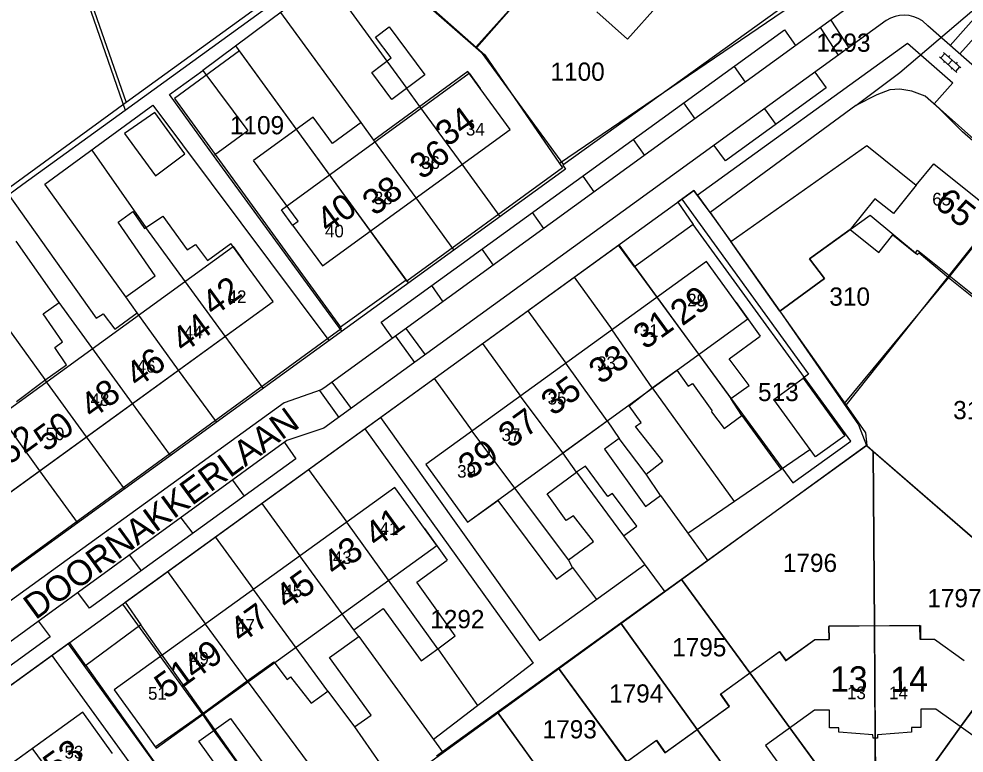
# Model space of a CAD drawing. Extents: x 148816 to 151297, y 399515 to 402500.
# Drawn here: x 149607 to 149700.3, y 400379.3 to 400451.8 of the extents above; entities that cross this region are included whole.
import ezdxf

# ---------------------------------------------------------------- set-up
doc = ezdxf.new("R2010")
doc.units = 0
for name, color, linetype in [('B01 Hoofdgebouw  [D] Norm', 7, 'Continuous'), ('B01 Hoofdgebouw  [T] Norm', 7, 'Continuous'), ('B01 hoofgebouw', 7, 'Continuous'), ('B02 Bijgebouw  [D] Norm', 7, 'Continuous'), ('B02 Bijgebouw  [T] Norm', 7, 'Continuous'), ('B07 Tussenmuur  [D] Norm', 7, 'Continuous'), ('G01 perceelsgrens', 7, 'Continuous'), ('S02 Open verharding  Norm', 7, 'Continuous'), ('T04 Haag heg  [D] Gem', 7, 'Continuous'), ('V00 Kant verharding algemeen  [T] Norm', 7, 'Continuous'), ('V00 Kant verharding algemeen secundair  [T] Gem', 7, 'Continuous'), ('Z01 perceelnummer', 7, 'Continuous'), ('Z02 huisnummer', 7, 'Continuous'), ('Z02 Huisnummer  [Tekst] Norm', 7, 'Continuous'), ('Z06 straatnaam', 7, 'Continuous')]:
    doc.layers.add(name, color=color, linetype=linetype)

msp = doc.modelspace()

# ---------------------------------------------------------------- linework, layer by layer
at = {"layer": 'B01 Hoofdgebouw  [D] Norm'}
for p, q in [((149634.541, 400431.857), (149630.161, 400437.867)), ((149634.01, 400431.47), (149634.541, 400431.857))]:
    msp.add_line(p, q, dxfattribs=at)
for points in [[(149626.206, 400438.351), (149621.85, 400444.376), (149625.142, 400446.746), (149629.575, 400440.771), (149626.282, 400438.376)], [(149652.54, 400444.97), (149651.318, 400446.638), (149642.033, 400439.87), (149640.776, 400441.593)], [(149640.776, 400441.593), (149637.939, 400439.525), (149636.029, 400442.145), (149630.161, 400437.867)], [(149605.857, 400434.609), (149614.619, 400422.278), (149615.307, 400422.706), (149616.466, 400421.2), (149618.662, 400422.788), (149617.554, 400424.396), (149620.438, 400426.463), (149616.789, 400431.773), (149618.218, 400432.806), (149619.376, 400431.147), (149621.188, 400432.356), (149623.58, 400429.012), (149624.421, 400429.54), (149625.605, 400427.957), (149627.914, 400429.66)], [(149682.127, 400422.976), (149686.543, 400426.192), (149685.056, 400428.133), (149691.029, 400432.444), (149695.729, 400428.577), (149695.883, 400428.729), (149698.763, 400426.296), (149701.898, 400423.786), (149701.846, 400423.634), (149703.943, 400421.867), (149702.79, 400420.273), (149702.536, 400420.427), (149702.332, 400420.25), (149705.445, 400417.636)], [(149703.527, 400432.216), (149698.763, 400426.296)], [(149606.741, 400414.039), (149609.549, 400416.132), (149611.667, 400417.67), (149610.51, 400419.38), (149611.275, 400419.934), (149609.362, 400422.691), (149610.97, 400423.826), (149606.716, 400429.876)], [(149629.14, 400427.97), (149627.914, 400429.66)], [(149680.16, 400425.77), (149682.127, 400422.976)], [(149677.8, 400423.81), (149680.191, 400420.505)], [(149651.284, 400402.113), (149654.288, 400404.27), (149660.081, 400396.482), (149661.664, 400397.642), (149661.262, 400398.381), (149663.713, 400400.197), (149661.748, 400402.751), (149661.008, 400402.272), (149659.145, 400404.927), (149662.055, 400407.045), (149666.689, 400400.764), (149667.991, 400401.722), (149665.598, 400404.939), (149665.139, 400404.662), (149662.923, 400407.65), (149662.029, 400407.045), (149660.695, 400408.96), (149665.06, 400412.137), (149666.243, 400410.401), (149664.813, 400409.342), (149668.867, 400403.674), (149670.322, 400404.758), (149668.913, 400406.851), (149670.573, 400408.138), (149667.876, 400411.56), (149668.438, 400411.964), (149667.229, 400413.623), (149669.527, 400415.389), (149671.952, 400417.128), (149673.06, 400415.546), (149673.493, 400415.823), (149675.407, 400413.167), (149675.381, 400413.015), (149676.64, 400411.381), (149678.376, 400412.641), (149677.294, 400414.325), (149679.081, 400415.611), (149677.117, 400418.267), (149680.191, 400420.505)], [(149668.913, 400406.851), (149666.243, 400410.401)], [(149650.1, 400403.75), (149651.284, 400402.113)], [(149647.03, 400401.5), (149649.284, 400398.374)], [(149620.449, 400379.915), (149625.062, 400383.195), (149629.529, 400386.447), (149632.158, 400388.312), (149633.468, 400386.576), (149633.8, 400386.828), (149635.841, 400384.248), (149637.475, 400385.408), (149640.12, 400381.884), (149641.778, 400383.043), (149637.649, 400388.737), (149640.533, 400390.829), (149640.055, 400391.493), (149642.939, 400393.586), (149646.691, 400388.403), (149648.35, 400389.587), (149650.061, 400390.874), (149646.259, 400396.184), (149649.284, 400398.374)], [(149619.31, 400381.49), (149620.449, 400379.915)], [(149626.17, 400381.561), (149632.113, 400373.416)]]:
    msp.add_lwpolyline(points, dxfattribs=at)
for points in [[(149617.404, 400440.514), (149620.477, 400436.352), (149623.362, 400438.52), (149620.39, 400442.606)], [(149627.879, 400382.72), (149633.797, 400374.575), (149632.113, 400373.391), (149632.239, 400373.212), (149629.916, 400371.523), (149625.659, 400377.243), (149626.604, 400377.923), (149624.74, 400380.477)]]:
    msp.add_lwpolyline(points, close=True, dxfattribs=at)
at = {"layer": 'B01 Hoofdgebouw  [T] Norm'}
for p, q in [((149667.07, 400449.84), (149670.13, 400453.27)), ((149664.05, 400452.54), (149667.07, 400449.84)), ((149655.48, 400440.93), (149652.54, 400444.97)), ((149636.96, 400427.43), (149655.48, 400440.93)), ((149677.28, 400429.86), (149690.71, 400439.32)), ((149690.71, 400439.32), (149695.6, 400435.4)), ((149695.6, 400435.4), (149697.32, 400437.53)), ((149697.32, 400437.53), (149710.09, 400427.27)), ((149634.01, 400431.47), (149636.96, 400427.43)), ((149680.16, 400425.77), (149677.28, 400429.86)), ((149632.08, 400423.92), (149629.14, 400427.97)), ((149674.87, 400427.86), (149647.17, 400407.8)), ((149677.8, 400423.81), (149674.87, 400427.86)), ((149604.42, 400403.85), (149632.08, 400423.92)), ((149647.17, 400407.8), (149650.1, 400403.75)), ((149644.11, 400405.55), (149616.38, 400385.54)), ((149647.03, 400401.5), (149644.11, 400405.55)), ((149616.38, 400385.54), (149619.31, 400381.49)), ((149613.28, 400383.33), (149585.54, 400363.31)), ((149616.21, 400379.27), (149613.28, 400383.33))]:
    msp.add_line(p, q, dxfattribs=at)
for points in [[(149664.107, 400376.374), (149669.936, 400380.583), (149670.814, 400379.367), (149677.162, 400383.951), (149676.284, 400385.167), (149682.081, 400389.353), (149682.719, 400388.469), (149685.581, 400390.535), (149687.013, 400390.565), (149687.01, 400391.875), (149696.01, 400391.895), (149696.013, 400390.555), (149697.413, 400390.558), (149700.335, 400388.455)], [(149702.442, 400380.136), (149697.513, 400383.627), (149696.041, 400383.626), (149696.042, 400381.816), (149695.132, 400381.815), (149695.132, 400381.375), (149691.771, 400381.097), (149691.76, 400380.774), (149691.329, 400380.773), (149691.321, 400381.1), (149687.948, 400381.376), (149687.954, 400381.813), (149687.044, 400381.813), (149687.043, 400383.533), (149685.554, 400383.553), (149680.702, 400380.056), (149685.285, 400373.727)]]:
    msp.add_lwpolyline(points, dxfattribs=at)
at = {"layer": 'B01 hoofgebouw'}
for points in [[(149664.05, 400452.54), (149667.07, 400449.84), (149670.13, 400453.27), (149668.31, 400454.9), (149672.21, 400459.26), (149660, 400470.17), (149656.1, 400465.8), (149654.26, 400467.44), (149651.19, 400464)], [(149634.01, 400431.47), (149632.91, 400432.977), (149651.439, 400446.483), (149652.54, 400444.97)], [(149634.01, 400431.47), (149636.96, 400427.43), (149655.48, 400440.93), (149652.54, 400444.97)], [(149680.16, 400425.77), (149677.28, 400429.86), (149690.71, 400439.32), (149695.6, 400435.4), (149697.32, 400437.53), (149710.09, 400427.27), (149708.34, 400425.09), (149710.22, 400423.57), (149707.09, 400419.68)], [(149695.6, 400435.4), (149693.34, 400432.601), (149691.512, 400434.07), (149689.065, 400431.025), (149691.898, 400428.75), (149693.298, 400430.493), (149695.517, 400428.71), (149695.734, 400428.98), (149701.792, 400424.113), (149701.559, 400423.823), (149703.935, 400421.915), (149702.526, 400420.161), (149705.533, 400417.745), (149707.09, 400419.68)], [(149689.065, 400431.025), (149685.056, 400428.133), (149686.543, 400426.192), (149682.127, 400422.976), (149680.16, 400425.77)], [(149601.48, 400407.9), (149600.475, 400409.284), (149628.135, 400429.354), (149629.14, 400427.97)], [(149601.48, 400407.9), (149604.42, 400403.85), (149632.08, 400423.92), (149629.14, 400427.97)], [(149677.8, 400423.81), (149674.87, 400427.86), (149647.17, 400407.8), (149650.1, 400403.75)], [(149650.1, 400403.75), (149651.273, 400402.134), (149678.973, 400422.194), (149677.8, 400423.81)], [(149647.03, 400401.5), (149644.11, 400405.55), (149616.38, 400385.54), (149619.31, 400381.49)], [(149619.31, 400381.49), (149620.533, 400379.8), (149648.254, 400399.803), (149647.03, 400401.5)], [(149685.558, 400390.496), (149686.983, 400390.525), (149686.957, 400391.803)], [(149695.956, 400391.896), (149686.958, 400391.803)], [(149697.398, 400390.516), (149695.979, 400390.54), (149695.957, 400391.896)], [(149682.696, 400388.43), (149685.558, 400390.496)], [(149700.319, 400388.412), (149697.398, 400390.516)], [(149679.155, 400387.219), (149682.058, 400389.314)], [(149682.044, 400389.333), (149682.688, 400388.454)], [(149664.099, 400376.351), (149669.897, 400380.537), (149670.776, 400379.318), (149677.135, 400383.908), (149676.256, 400385.126), (149679.155, 400387.219)], [(149616.21, 400379.27), (149613.28, 400383.33), (149585.54, 400363.31), (149588.47, 400359.25)], [(149702.442, 400380.136), (149697.513, 400383.627), (149696.041, 400383.626), (149696.042, 400381.816), (149695.132, 400381.815), (149695.132, 400381.375), (149691.771, 400381.097), (149691.76, 400380.774), (149691.329, 400380.773), (149691.321, 400381.1), (149687.948, 400381.376), (149687.954, 400381.813), (149687.044, 400381.813), (149687.043, 400383.533), (149685.554, 400383.553), (149680.702, 400380.056), (149685.285, 400373.727)]]:
    msp.add_lwpolyline(points, dxfattribs=at)
at = {"layer": 'B02 Bijgebouw  [D] Norm'}
msp.add_line((149643.316, 400447.67), (149645.297, 400444.954), dxfattribs=at)
msp.add_lwpolyline([(149643.53, 400451.045), (149647.074, 400446.314), (149643.818, 400443.875), (149641.817, 400446.546), (149643.733, 400447.982), (149642.19, 400450.04)], close=True, dxfattribs=at)
at = {"layer": 'B02 Bijgebouw  [T] Norm'}
msp.add_lwpolyline([(149684.427, 400416.335), (149688.536, 400410.655), (149685.652, 400408.568), (149681.543, 400414.248)], close=True, dxfattribs=at)
at = {"layer": 'B07 Tussenmuur  [D] Norm'}
for p, q in [((149650.746, 400437.479), (149646.587, 400443.185)), ((149650.746, 400437.479), (149646.587, 400443.185)), ((149641.715, 400430.896), (149634.353, 400440.996)), ((149641.715, 400430.896), (149634.353, 400440.996)), ((149646.194, 400434.161), (149642.033, 400439.87)), ((149646.194, 400434.161), (149642.033, 400439.87)), ((149627.341, 400420.481), (149619.529, 400431.248)), ((149627.341, 400420.481), (149619.529, 400431.248)), ((149669.994, 400424.329), (149677.294, 400414.325)), ((149669.994, 400424.329), (149677.294, 400414.325)), ((149618.206, 400413.853), (149610.97, 400423.826)), ((149618.206, 400413.853), (149610.97, 400423.826)), ((149622.752, 400417.152), (149618.662, 400422.788)), ((149622.752, 400417.152), (149618.662, 400422.788)), ((149669.527, 400415.389), (149665.567, 400421.123)), ((149669.527, 400415.389), (149665.567, 400421.123)), ((149665.06, 400412.137), (149661.002, 400417.817)), ((149665.06, 400412.137), (149661.002, 400417.817)), ((149609.04, 400407.202), (149601.807, 400417.17)), ((149609.04, 400407.202), (149601.807, 400417.17)), ((149613.666, 400410.559), (149609.555, 400416.224)), ((149613.666, 400410.559), (149609.555, 400416.224)), ((149660.695, 400408.96), (149656.507, 400414.562)), ((149660.695, 400408.96), (149656.507, 400414.562)), ((149661.262, 400398.381), (149651.748, 400411.115)), ((149661.262, 400398.381), (149651.748, 400411.115)), ((149648.35, 400389.587), (149639.364, 400402.126)), ((149648.35, 400389.587), (149639.364, 400402.126)), ((149640.055, 400391.493), (149634.727, 400398.779)), ((149640.055, 400391.493), (149634.727, 400398.779)), ((149637.475, 400385.408), (149630.135, 400395.465)), ((149637.475, 400385.408), (149630.135, 400395.465)), ((149629.529, 400386.447), (149625.399, 400392.048)), ((149629.529, 400386.447), (149625.399, 400392.048)), ((149691.457, 400391.849), (149691.544, 400380.774)), ((149691.457, 400391.849), (149691.544, 400380.774)), ((149625.062, 400383.195), (149620.971, 400388.853)), ((149625.062, 400383.195), (149620.971, 400388.853)), ((149679.155, 400387.219), (149683.12, 400381.799)), ((149679.155, 400387.219), (149683.12, 400381.799)), ((149703.883, 400387.264), (149699.961, 400381.893)), ((149703.883, 400387.264), (149699.961, 400381.893)), ((149673.965, 400381.62), (149682.258, 400370.253)), ((149673.965, 400381.62), (149682.258, 400370.253))]:
    msp.add_line(p, q, dxfattribs=at)
msp.add_lwpolyline([(149612.301, 400374.069), (149612.479, 400374.119), (149608.298, 400379.788)], dxfattribs=at)
msp.add_lwpolyline([(149612.301, 400374.069), (149612.479, 400374.119), (149608.298, 400379.788)], dxfattribs=at)
at = {"layer": 'G01 perceelsgrens'}
for points in [[(149599.495, 400494.401), (149606.475, 400474.559), (149617.476, 400442.841)], [(149669.257, 400468.442), (149652.171, 400449.011)], [(149689.638, 400443.297), (149693.972, 400446.553), (149706.878, 400457.592), (149711.53, 400460.677)], [(149617.476, 400442.841), (149640.368, 400459.456)], [(149641.758, 400458.226), (149652.171, 400449.011)], [(149683.433, 400455.729), (149683.367, 400453.207), (149660.349, 400437.563)], [(149645.215, 400426.038), (149628.775, 400448.691), (149622.332, 400443.984), (149638.729, 400421.371)], [(149652.171, 400449.011), (149652.983, 400448.292), (149660.349, 400437.563)], [(149706.05, 400435.536), (149700.147, 400440.671), (149697.858, 400442.978), (149696.463, 400444.213), (149695.149, 400444.702), (149693.983, 400444.908), (149692.988, 400444.821), (149691.687, 400444.348), (149689.638, 400443.297)], [(149596.625, 400427.624), (149607.367, 400435.504), (149617.476, 400442.841)], [(149689.638, 400443.297), (149675.247, 400432.713)], [(149660.651, 400437.143), (149645.286, 400425.94)], [(149660.349, 400437.563), (149660.651, 400437.143)], [(149688.673, 400413.674), (149706.05, 400435.536)], [(149675.247, 400432.713), (149673.64, 400434.89), (149672.065, 400433.751)], [(149672.065, 400433.751), (149673.578, 400431.518)], [(149675.247, 400432.713), (149688.673, 400413.674)], [(149667.765, 400427.338), (149683.397, 400406.012), (149689.121, 400410.109), (149673.578, 400431.518)], [(149673.578, 400431.518), (149667.765, 400427.338)], [(149617.473, 400394.208), (149666.185, 400429.492)], [(149667.765, 400427.338), (149666.185, 400429.492)], [(149645.215, 400426.038), (149638.729, 400421.371)], [(149645.286, 400425.94), (149645.215, 400426.038)], [(149638.729, 400421.371), (149638.811, 400421.22)], [(149638.811, 400421.22), (149581.911, 400379.736)], [(149688.673, 400413.674), (149690.594, 400410.95), (149690.717, 400409.68)], [(149690.717, 400409.68), (149690.696, 400409.656), (149672.404, 400396.447)], [(149690.717, 400409.68), (149691.33, 400409.149)], [(149691.33, 400409.149), (149701.135, 400400.643)], [(149691.457, 400391.849), (149691.33, 400409.149)], [(149672.404, 400396.447), (149666.416, 400392.123)], [(149679.155, 400387.219), (149672.404, 400396.447)], [(149617.473, 400394.208), (149619.015, 400391.985)], [(149695.388, 400375.496), (149699.961, 400381.893), (149703.883, 400387.264), (149708.816, 400393.98)], [(149613.58, 400387.97), (149627.713, 400368.042), (149633.167, 400371.916), (149619.015, 400391.985)], [(149619.015, 400391.985), (149613.58, 400387.97)], [(149666.416, 400392.123), (149660.277, 400387.69)], [(149684.293, 400367.463), (149673.965, 400381.62), (149666.416, 400392.123)], [(149691.576, 400375.796), (149691.457, 400391.849)], [(149586.38, 400371.686), (149611.981, 400390.23)], [(149613.58, 400387.97), (149611.981, 400390.23)], [(149660.277, 400387.69), (149654.248, 400383.337)], [(149678.205, 400363.068), (149670.976, 400373.041), (149667.003, 400378.447), (149660.277, 400387.69)], [(149687.718, 400375.48), (149683.12, 400381.799), (149679.155, 400387.219)], [(149654.248, 400383.337), (149648.22, 400378.984)], [(149672.135, 400358.681), (149661.816, 400372.85), (149654.248, 400383.337)]]:
    msp.add_lwpolyline(points, dxfattribs=at)
at = {"layer": 'S02 Open verharding  Norm'}
for p, q in [((149698.006, 400447.986), (149698.404, 400448.435)), ((149698.291, 400448.534), (149700.013, 400447.009)), ((149697.893, 400448.085), (149699.615, 400446.56)), ((149698.38, 400447.654), (149698.28, 400447.542)), ((149699.152, 400447.772), (149698.754, 400447.322)), ((149698.877, 400448.215), (149698.778, 400448.103)), ((149699.626, 400447.552), (149699.526, 400447.44)), ((149699.128, 400446.991), (149699.029, 400446.879)), ((149699.502, 400446.659), (149699.9, 400447.108))]:
    msp.add_line(p, q, dxfattribs=at)
at = {"layer": 'T04 Haag heg  [D] Gem'}
for p, q in [((149599.508, 400495.355), (149617.566, 400443.567)), ((149639.868, 400459.758), (149617.573, 400443.572)), ((149660.669, 400458.631), (149652.07, 400449.026)), ((149637.347, 400455.858), (149625.142, 400446.746)), ((149637.347, 400455.858), (149643.316, 400447.67)), ((149640.776, 400441.593), (149632.833, 400452.488)), ((149634.353, 400440.996), (149628.392, 400449.172)), ((149646.587, 400443.185), (149645.297, 400444.954)), ((149617.573, 400443.572), (149596.619, 400428.278)), ((149609.534, 400435.528), (149620.188, 400443.327)), ((149614.165, 400438.867), (149619.529, 400431.248)), ((149654.499, 400432.331), (149650.746, 400437.479)), ((149617.554, 400424.396), (149609.534, 400435.528)), ((149673.966, 400434.444), (149677.28, 400429.86)), ((149649.94, 400429.024), (149646.194, 400434.161)), ((149645.453, 400425.769), (149641.715, 400430.896)), ((149600.398, 400428.824), (149609.555, 400416.224)), ((149666.231, 400429.524), (149669.994, 400424.329)), ((149661.805, 400426.317), (149665.567, 400421.123)), ((149698.763, 400426.296), (149688.453, 400413.813)), ((149657.24, 400423.011), (149661.002, 400417.817)), ((149631.084, 400415.347), (149627.341, 400420.481)), ((149652.745, 400419.755), (149656.507, 400414.562)), ((149626.495, 400412.018), (149622.752, 400417.152)), ((149647.986, 400416.308), (149651.748, 400411.115)), ((149669.527, 400415.389), (149677.603, 400404.157)), ((149621.948, 400408.72), (149618.206, 400413.853)), ((149678.376, 400412.641), (149682.236, 400407.344)), ((149617.408, 400405.426), (149613.666, 400410.559)), ((149673.04, 400401.018), (149685.081, 400409.301)), ((149691.33, 400409.149), (149691.457, 400391.849)), ((149635.593, 400407.332), (149639.364, 400402.126)), ((149612.781, 400402.07), (149609.04, 400407.202)), ((149670.322, 400404.758), (149675.007, 400398.311)), ((149630.962, 400403.977), (149634.727, 400398.779)), ((149666.689, 400400.764), (149670.773, 400395.237)), ((149626.376, 400400.655), (149630.135, 400395.465)), ((149621.646, 400397.229), (149625.399, 400392.048)), ((149661.664, 400397.642), (149664.02, 400394.478)), ((149672.404, 400396.447), (149679.155, 400387.219)), ((149617.224, 400394.026), (149620.971, 400388.853)), ((149666.416, 400392.123), (149673.965, 400381.62)), ((149640.533, 400390.829), (149648.863, 400379.332)), ((149648.35, 400389.587), (149652.282, 400384.008)), ((149660.277, 400387.69), (149667.022, 400378.478)), ((149629.529, 400386.447), (149637.851, 400375.206)), ((149625.062, 400383.195), (149626.17, 400381.561)), ((149654.248, 400383.337), (149661.807, 400372.844)), ((149640.12, 400381.884), (149644.23, 400375.97)), ((149683.12, 400381.799), (149687.718, 400375.48)), ((149699.961, 400381.893), (149695.388, 400375.496)), ((149691.544, 400380.774), (149691.576, 400375.796))]:
    msp.add_line(p, q, dxfattribs=at)
for points in [[(149639.868, 400459.758), (149652.623, 400448.54), (149660.748, 400437.423)], [(149682.127, 400422.976), (149689.886, 400411.738), (149690.68, 400409.687), (149716.368, 400387.404), (149735.005, 400375.5)], [(149642.683, 400412.467), (149658.399, 400390.421), (149668.79, 400397.92)], [(149641.138, 400411.348), (149657.773, 400388.187), (149647.919, 400380.635)], [(149690.68, 400409.687), (149645.381, 400376.805), (149611.62, 400352.555)], [(149611.836, 400390.105), (149627.651, 400368.244), (149642.538, 400378.405)], [(149610.216, 400388.932), (149626.133, 400366.971), (149607.063, 400352.953)]]:
    msp.add_lwpolyline(points, dxfattribs=at)
at = {"layer": 'V00 Kant verharding algemeen  [T] Norm'}
for p, q in [((149716.24, 400433.98), (149696.73, 400451.17)), ((149673.96, 400434.44), (149694.72, 400449.45)), ((149694.72, 400449.45), (149699.2, 400445.51)), ((149699.2, 400445.51), (149697.38, 400443.45)), ((149620.188, 400443.327), (149637.581, 400420.06)), ((149697.38, 400443.45), (149719.66, 400423.51)), ((149638.863, 400420.99), (149626.206, 400438.351)), ((149561.383, 400353.578), (149673.64, 400434.89)), ((149673.64, 400434.89), (149673.96, 400434.44))]:
    msp.add_line(p, q, dxfattribs=at)
for points in [[(149683.03, 400453.46), (149660.686, 400437.378), (149660.952, 400437.012), (149579.946, 400378.253), (149580.045, 400378.116), (149555.602, 400360.572)], [(149689.364, 400453.335), (149637.091, 400415.374), (149636.834, 400415.188), (149633.16, 400413.903), (149586.836, 400380.371), (149584.735, 400377.431), (149557.956, 400358.172)], [(149692.632, 400451.684), (149637.083, 400411.392), (149633.449, 400410.175), (149590.434, 400378.907), (149588.204, 400375.854), (149560.275, 400355.791)], [(149696.73, 400451.17), (149696.2, 400451.637)], [(149672.44, 400434.021), (149684.959, 400416.728), (149684.427, 400416.335)]]:
    msp.add_lwpolyline(points, dxfattribs=at)
msp.add_arc((149694.381, 400449.038), 3.172, 55.00355, 123.47572, dxfattribs=at)
at = {"layer": 'V00 Kant verharding algemeen secundair  [T] Gem'}
for p, q in [((149702.296, 400452.989), (149698.952, 400449.212)), ((149703.245, 400452.155), (149699.899, 400448.378)), ((149687.146, 400451.724), (149688.928, 400448.998)), ((149686.117, 400450.977), (149687.899, 400448.251)), ((149677.602, 400447.146), (149678.696, 400445.588)), ((149672.622, 400443.537), (149673.719, 400441.974)), ((149680.605, 400442.959), (149681.721, 400441.422)), ((149667.641, 400439.928), (149668.742, 400438.359)), ((149662.661, 400436.319), (149663.766, 400434.745)), ((149657.681, 400432.71), (149658.789, 400431.131)), ((149652.7, 400429.1), (149653.811, 400427.516)), ((149647.719, 400425.491), (149648.835, 400423.902)), ((149644.154, 400420.503), (149646.048, 400417.895)), ((149645.191, 400421.256), (149647.084, 400418.646)), ((149637.889, 400415.954), (149639.779, 400413.348)), ((149636.655, 400415.125), (149638.576, 400412.475)), ((149628.063, 400406.26), (149629.231, 400404.679)), ((149622.975, 400402.562), (149624.138, 400400.988)), ((149617.888, 400398.863), (149619.045, 400397.297))]:
    msp.add_line(p, q, dxfattribs=at)
for points in [[(149643.887, 400420.309), (149642.743, 400421.885), (149682.583, 400450.755), (149683.673, 400449.202)], [(149685.583, 400446.571), (149686.699, 400445.033), (149676.743, 400437.812), (149675.626, 400439.349)], [(149633.191, 400409.988), (149634.342, 400408.383), (149613.951, 400393.606), (149612.8, 400395.164)], [(149608.891, 400392.358), (149610.077, 400390.794), (149591.852, 400377.573), (149590.72, 400379.107)]]:
    msp.add_lwpolyline(points, dxfattribs=at)

# ---------------------------------------------------------------- texts
at = {"layer": 'Z01 perceelnummer'}
for s, p in [('1293', (149685.727, 400448.594)), ('1100', (149659.473, 400445.729)), ('1109', (149627.816, 400440.441)), ('310', (149687.014, 400423.507)), ('513', (149679.967, 400414.081)), ('311', (149699.236, 400412.292)), ('1796', (149682.422, 400397.201)), ('1797', (149696.691, 400393.709)), ('1292', (149647.602, 400391.64)), ('1795', (149671.489, 400388.859)), ('1794', (149665.257, 400384.292)), ('1793', (149658.697, 400380.754))]:
    msp.add_text(s, height=1.8, dxfattribs=at).set_placement(p)
at = {"layer": 'Z02 huisnummer'}
for s, rotation, p in [('34', 36.09057, (149649.29, 400439.139)), ('36', 36.01053, (149646.756, 400435.898)), ('38', 36.01053, (149642.075, 400432.311)), ('40', 36.09057, (149637.537, 400430.572)), ('65', 321.25072, (149697.261, 400433.407)), ('42', 35.96416, (149626.197, 400422.37)), ('29', 35.93052, (149672.483, 400421.439)), ('44', 36.01053, (149623.224, 400418.768)), ('31', 35.93052, (149668.822, 400419.096)), ('33', 35.93052, (149664.433, 400415.658)), ('46', 36.01053, (149618.68, 400415.333)), ('48', 36.01053, (149614.199, 400412.247)), ('35', 35.93052, (149659.718, 400412.548)), ('50', 36.01053, (149609.632, 400408.996)), ('37', 35.93052, (149655.509, 400409.338)), ('52', 35.96416, (149605.991, 400407.708)), ('39', 35.93052, (149651.538, 400406.271)), ('41', 35.80411, (149642.274, 400399.539)), ('43', 35.80411, (149638.159, 400396.698)), ('45', 35.80411, (149633.445, 400393.386)), ('47', 35.80411, (149628.934, 400390.077)), ('49', 35.80411, (149624.322, 400386.466)), ('51', 35.80411, (149621.526, 400384.568)), ('14', 0.57294, (149693.045, 400385.344)), ('53', 35.80411, (149610.537, 400376.664))]:
    msp.add_text(s, height=2.5, rotation=rotation, dxfattribs=at).set_placement(p)
msp.add_text('13', height=2.5, dxfattribs=at).set_placement((149687.078, 400385.375))
at = {"layer": 'Z02 Huisnummer  [Tekst] Norm'}
for s, p in [('34', (149651.122, 400440.321)), ('36', (149646.7, 400437.023)), ('38', (149642.035, 400433.522)), ('65', (149697.175, 400433.41)), ('40', (149637.206, 400430.259)), ('42', (149627.588, 400423.769)), ('29', (149672.98, 400423.437)), ('44', (149623.268, 400420.283)), ('31', (149668.296, 400420.418)), ('33', (149664.076, 400417.245)), ('46', (149618.604, 400416.892)), ('48', (149614.051, 400413.609)), ('35', (149659.19, 400413.744)), ('50', (149609.608, 400410.218)), ('37', (149654.637, 400410.134)), ('39', (149650.258, 400406.517)), ('41', (149642.595, 400400.86)), ('43', (149637.979, 400397.989)), ('45', (149633.093, 400394.707)), ('47', (149628.429, 400391.315)), ('49', (149623.876, 400388.033)), ('51', (149619.735, 400384.577)), ('13', (149688.757, 400384.629)), ('14', (149692.911, 400384.629)), ('53', (149611.479, 400378.771))]:
    msp.add_text(s, height=1.25, dxfattribs=at).set_placement(p)
at = {"layer": 'Z06 straatnaam'}
msp.add_text('DOORNAKKERLAAN', height=2.5, rotation=36.17064, dxfattribs=at).set_placement((149608.622, 400392.407))

doc.saveas('drawing.dxf')
